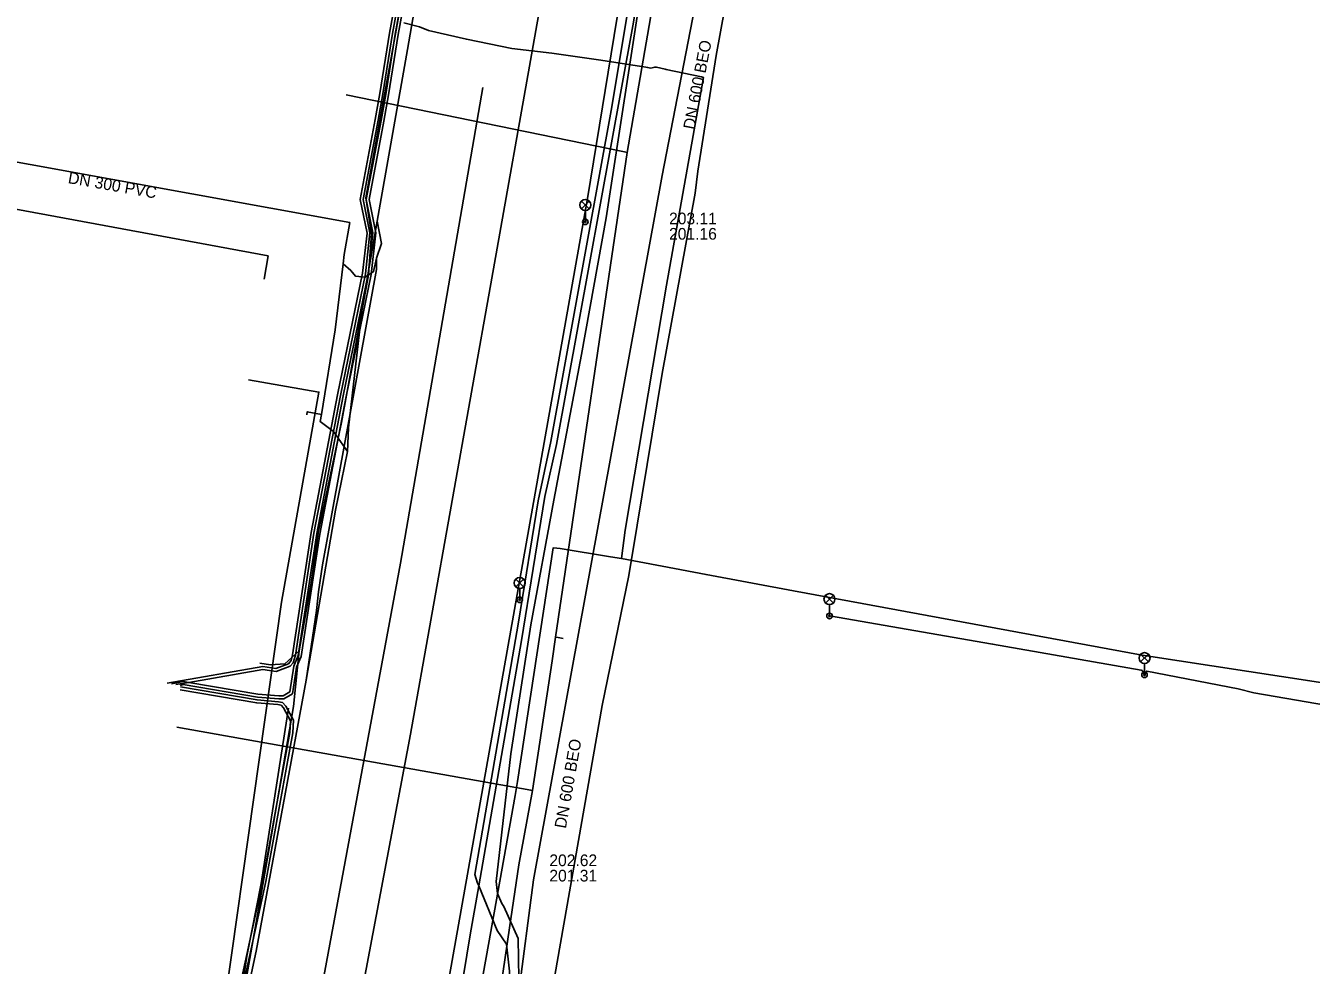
# Model space of a CAD drawing. Extents: x -596228 to -595156, y -1161235 to -1159373.
# Drawn here: x -595929.1 to -595841.1, y -1160278.8 to -1160214.5 of the extents above; entities that cross this region are included whole.
import ezdxf

# ---------------------------------------------------------------- set-up
doc = ezdxf.new("R2010")
doc.units = 0
for name, color, linetype in [('Vrstva 1', 7, 'Continuous'), ('Vrstva 12', 7, 'Continuous'), ('Vrstva 14', 7, 'Continuous'), ('Vrstva 19', 7, 'Continuous'), ('Vrstva 33', 7, 'Continuous'), ('Vrstva 4', 7, 'Continuous'), ('Vrstva 42', 7, 'Continuous'), ('Vrstva 44', 7, 'Continuous'), ('Vrstva 5', 7, 'Continuous'), ('Vrstva 53', 7, 'Continuous'), ('Vrstva 55', 7, 'Continuous'), ('Vrstva 58', 7, 'Continuous'), ('Vrstva 9', 7, 'Continuous')]:
    doc.layers.add(name, color=color, linetype=linetype)

msp = doc.modelspace()

# ---------------------------------------------------------------- linework, layer by layer
at = {"layer": 'Vrstva 1'}
for p, q in [((-595876.82, -1160179.87), (-595885.54, -1160224.74)), ((-595897.82, -1160218.72), (-595903.46, -1160251.27)), ((-595885.54, -1160224.74), (-595894.35, -1160272.94)), ((-595912.774, -1160231.832), (-595912.502, -1160230.231)), ((-595903.46, -1160251.27), (-595910.91, -1160291.43)), ((-595894.35, -1160272.94), (-595897.18, -1160294.69))]:
    msp.add_line(p, q, dxfattribs=at)
msp.add_lwpolyline([(-595912.502, -1160230.231), (-595937.093, -1160225.712), (-595938.437, -1160225.792)], dxfattribs=at)
at = {"layer": 'Vrstva 12'}
for p, q in [((-595905.09, -1160230.41), (-595904.75, -1160229.39)), ((-595907.09, -1160243.62), (-595908.03, -1160242.26)), ((-595909.07, -1160253.23), (-595909.2, -1160254.51)), ((-595909.2, -1160254.51), (-595909.92, -1160259.27)), ((-595909.92, -1160259.27), (-595913.327, -1160277.82)), ((-595913.327, -1160277.82), (-595916.466, -1160292.479))]:
    msp.add_line(p, q, dxfattribs=at)
for points in [[(-595897.36, -1160184.72), (-595897.52, -1160185.49), (-595898.28, -1160189.11), (-595902.98, -1160216.12), (-595905.04, -1160227.87), (-595904.75, -1160229.39)], [(-595906.85, -1160231.25), (-595907.387, -1160230.78), (-595907.31, -1160230.14), (-595906.92, -1160227.97), (-595939.63, -1160222.04), (-595961.4, -1160213.41), (-595962.62, -1160212.93), (-595961.32, -1160205.66)], [(-595905.04, -1160227.87), (-595906.05, -1160233.63), (-595906.1, -1160234.06), (-595907.02, -1160242.01), (-595907.09, -1160243.62)], [(-595909.07, -1160253.23), (-595908.79, -1160251.39), (-595905.09, -1160231.17), (-595905.09, -1160230.41)], [(-595908.86, -1160241.09), (-595907.93, -1160235.31), (-595907.387, -1160230.78)], [(-595905.86, -1160231.69), (-595906.54, -1160231.63), (-595906.85, -1160231.25)], [(-595905.09, -1160230.41), (-595905.3, -1160231.32), (-595905.86, -1160231.69)], [(-595908.86, -1160241.09), (-595909.84, -1160240.91), (-595909.87, -1160241.11)], [(-595908.03, -1160242.26), (-595908.94, -1160241.58), (-595908.86, -1160241.09)], [(-595907.09, -1160243.62), (-595907.89, -1160247.65), (-595909.92, -1160259.27)]]:
    msp.add_lwpolyline(points, dxfattribs=at)
at = {"layer": 'Vrstva 14'}
for p, q in [((-595892.847, -1160256.335), (-595892.657, -1160256.359)), ((-595892.657, -1160256.359), (-595892.328, -1160256.414))]:
    msp.add_line(p, q, dxfattribs=at)
for points in [[(-595903.525, -1160327.591), (-595903.438, -1160327.11), (-595895.992, -1160276.218), (-595895.362, -1160271.913), (-595894.416, -1160266.829), (-595893.077, -1160257.958), (-595892.847, -1160256.335), (-595887.94, -1160223.167), (-595881.65, -1160186.81), (-595876.814, -1160159.541), (-595869.649, -1160117.522), (-595863.209, -1160078.856), (-595858.091, -1160048.124), (-595857.576, -1160045.207), (-595855.994, -1160045.422), (-595855.543, -1160042.523), (-595857.05, -1160042.292), (-595850.5, -1160006.311), (-595840.026, -1160007.969)], [(-595887.94, -1160223.167), (-595888.124, -1160223.122), (-595907.174, -1160219.223)], [(-595894.416, -1160266.829), (-595894.54, -1160266.81), (-595918.761, -1160262.489)]]:
    msp.add_lwpolyline(points, dxfattribs=at)
at = {"layer": 'Vrstva 19'}
for points in [[(-595903.221, -1160214.288), (-595902.141, -1160214.568), (-595901.538, -1160214.811), (-595898.944, -1160215.422), (-595895.836, -1160216.053), (-595893.093, -1160216.381), (-595889.745, -1160216.854), (-595886.651, -1160217.335), (-595886.538, -1160217.348), (-595886.31, -1160217.396), (-595886.044, -1160217.328), (-595885.94, -1160217.34), (-595885.329, -1160217.474), (-595885.273, -1160217.492), (-595882.844, -1160217.996), (-595882.722, -1160218.029), (-595885.239, -1160232.238), (-595888.066, -1160249.019), (-595888.326, -1160250.942)], [(-595885.548, -1160251.465), (-595888.326, -1160250.942), (-595889.076, -1160250.833), (-595892.522, -1160250.265), (-595892.744, -1160250.249), (-595892.999, -1160250.212), (-595895.437, -1160266.212), (-595895.603, -1160267.172), (-595897.424, -1160277.35), (-595899.243, -1160287.517)], [(-595807.996, -1160263.637), (-595810.557, -1160263.662), (-595816.559, -1160263.81), (-595837.554, -1160259.982), (-595840.612, -1160259.413), (-595852.684, -1160257.565), (-595876.553, -1160253.153), (-595882.538, -1160252.052), (-595885.548, -1160251.465)]]:
    msp.add_lwpolyline(points, dxfattribs=at)
at = {"layer": 'Vrstva 33'}
for p, q in [((-595891.065, -1160226.495), (-595890.535, -1160227.025)), ((-595891.065, -1160227.025), (-595890.535, -1160226.495)), ((-595890.8, -1160227.91), (-595890.8, -1160227.135)), ((-595895.559, -1160252.36), (-595895.029, -1160252.89)), ((-595895.559, -1160252.89), (-595895.029, -1160252.36)), ((-595895.294, -1160253.775), (-595895.294, -1160253)), ((-595874.355, -1160253.465), (-595873.825, -1160253.995)), ((-595874.355, -1160253.995), (-595873.825, -1160253.465)), ((-595874.09, -1160254.88), (-595874.09, -1160254.105)), ((-595852.791, -1160257.498), (-595852.261, -1160258.028)), ((-595852.791, -1160258.028), (-595852.261, -1160257.498)), ((-595852.526, -1160258.913), (-595852.526, -1160258.138))]:
    msp.add_line(p, q, dxfattribs=at)
for centre, radius in [((-595890.8, -1160226.76), 0.375), ((-595890.8, -1160227.91), 0.19), ((-595890.8, -1160227.91), 0.05), ((-595895.294, -1160252.625), 0.375), ((-595895.294, -1160253.775), 0.19), ((-595895.294, -1160253.775), 0.05), ((-595874.09, -1160253.73), 0.375), ((-595874.09, -1160254.88), 0.19), ((-595874.09, -1160254.88), 0.05), ((-595852.526, -1160257.763), 0.375), ((-595852.526, -1160258.913), 0.19), ((-595852.526, -1160258.913), 0.05)]:
    msp.add_circle(centre, radius, dxfattribs=at)
at = {"layer": 'Vrstva 42'}
for points in [[(-595899.339, -1160297.503), (-595902.099, -1160297.56), (-595902.383, -1160297.165), (-595902.586, -1160296.883), (-595902.568, -1160296.769), (-595901.316, -1160288.727), (-595900.471, -1160287.553), (-595898.687, -1160276.707), (-595898.101, -1160273.351), (-595895.17, -1160256.55), (-595893.577, -1160246.717), (-595892.781, -1160243.14), (-595887.556, -1160214.494), (-595883.249, -1160189.231), (-595883.208, -1160189), (-595882.655, -1160185.86), (-595879.849, -1160169.95), (-595878.786, -1160163.811), (-595878.313, -1160161.147), (-595878.278, -1160160.95), (-595875.884, -1160147.461), (-595871.512, -1160122.724)], [(-595899.318, -1160297.883), (-595899.891, -1160298.432), (-595899.423, -1160299.009), (-595897.224, -1160298.688), (-595896.375, -1160297.645), (-595896.521, -1160294.611), (-595896.622, -1160292.035), (-595896.678, -1160291.316), (-595895.995, -1160279.177), (-595896.207, -1160277.347), (-595896.845, -1160276.413), (-595898.101, -1160273.351), (-595898.174, -1160273.174), (-595898.37, -1160272.566), (-595895.372, -1160255.298), (-595894.03, -1160247.01), (-595893.153, -1160242.953), (-595888.976, -1160220.051), (-595884.001, -1160189.966)], [(-595902.605, -1160206.328), (-595904.206, -1160214.999), (-595904.856, -1160219.13), (-595905.175, -1160220.916), (-595906.206, -1160226.392), (-595905.743, -1160228.683), (-595906.057, -1160231.433), (-595907.764, -1160239.752), (-595909.576, -1160249.179), (-595910.847, -1160257.535), (-595910.946, -1160257.929), (-595911.122, -1160258.156), (-595911.981, -1160258.477), (-595912.871, -1160258.349), (-595919.421, -1160259.479)], [(-595902.212, -1160206.397), (-595903.811, -1160215.067), (-595904.461, -1160219.197), (-595904.782, -1160220.988), (-595905.798, -1160226.389), (-595905.339, -1160228.666), (-595905.661, -1160231.496), (-595907.372, -1160239.83), (-595909.181, -1160249.247), (-595910.451, -1160257.595), (-595910.764, -1160258.321), (-595911.032, -1160260.078), (-595911.483, -1160260.346), (-595911.775, -1160260.351), (-595913.212, -1160260.232), (-595917.946, -1160259.427), (-595918.337, -1160259.361), (-595919.13, -1160259.53)], [(-595902.409, -1160206.363), (-595904.009, -1160215.033), (-595904.659, -1160219.163), (-595904.978, -1160220.952), (-595906.002, -1160226.391), (-595905.541, -1160228.674), (-595905.859, -1160231.464), (-595907.568, -1160239.791), (-595909.379, -1160249.213), (-595910.649, -1160257.565), (-595910.809, -1160258.078), (-595910.998, -1160258.324), (-595911.959, -1160258.683), (-595912.869, -1160258.551), (-595917.946, -1160259.427), (-595918.839, -1160259.581)], [(-595902.015, -1160206.432), (-595903.614, -1160215.101), (-595904.264, -1160219.23), (-595904.585, -1160221.024), (-595905.594, -1160226.388), (-595905.137, -1160228.657), (-595905.463, -1160231.527), (-595907.176, -1160239.869), (-595908.984, -1160249.281), (-595910.257, -1160257.651), (-595910.57, -1160258.376), (-595910.848, -1160260.202), (-595911.427, -1160260.545), (-595911.782, -1160260.551), (-595913.237, -1160260.431), (-595918.333, -1160259.564), (-595918.543, -1160259.635)], [(-595918.537, -1160259.935), (-595913.288, -1160260.828), (-595911.837, -1160260.948), (-595911.623, -1160260.992), (-595911.462, -1160261.169), (-595910.972, -1160262.063), (-595911.019, -1160262.848), (-595911.438, -1160265.082), (-595912.868, -1160273.011), (-595914.988, -1160282.762), (-595915.239, -1160284.476), (-595915.239, -1160284.478), (-595915.289, -1160284.826)], [(-595918.504, -1160259.738), (-595913.263, -1160260.629), (-595911.808, -1160260.75), (-595911.519, -1160260.809), (-595911.298, -1160261.051), (-595910.768, -1160262.017), (-595910.821, -1160262.872), (-595911.242, -1160265.118), (-595912.672, -1160273.05), (-595914.792, -1160282.798), (-595915.041, -1160284.502), (-595915.041, -1160284.504), (-595915.091, -1160284.854)]]:
    msp.add_lwpolyline(points, dxfattribs=at)
at = {"layer": 'Vrstva 44'}
for points in [[(-595896.897, -1160273.045), (-595895.909, -1160264.308), (-595894.529, -1160255.491), (-595892.955, -1160246.953), (-595891.073, -1160236.98), (-595889.376, -1160227.647), (-595886.84, -1160211.177), (-595885.783, -1160204.31), (-595884.451, -1160196.692), (-595882.21, -1160184.038), (-595880.223, -1160171.529), (-595878.837, -1160163.768), (-595878.228, -1160160.447), (-595878.1, -1160159.1), (-595877.88, -1160157.51)], [(-595896.897, -1160273.045), (-595896.806, -1160273.86), (-595896.521, -1160274.563), (-595896.383, -1160274.768), (-595895.399, -1160276.958), (-595895.348, -1160279.684)]]:
    msp.add_lwpolyline(points, dxfattribs=at)
at = {"layer": 'Vrstva 5'}
msp.add_line((-595911.59, -1160253.94), (-595915.382, -1160280.667), dxfattribs=at)
msp.add_lwpolyline([(-595913.851, -1160238.732), (-595909.039, -1160239.565), (-595911.59, -1160253.94)], dxfattribs=at)
at = {"layer": 'Vrstva 53'}
for points in [[(-595878.72, -1160160.38), (-595878.9, -1160160.76), (-595879.19, -1160160.96), (-595882.85, -1160160.12), (-595885.65, -1160159.55), (-595888.42, -1160159.22), (-595893.19, -1160158.25), (-595893.53, -1160158.31), (-595893.95, -1160158.7), (-595894.87, -1160163.74), (-595896.89, -1160175), (-595897.42, -1160178.86), (-595898.79, -1160185.95), (-595898.99, -1160187.07), (-595901.26, -1160200.17), (-595903.5, -1160213.4), (-595905.82, -1160226.28), (-595905.44, -1160228.74)], [(-595905.44, -1160228.74), (-595905.65, -1160231.54), (-595907.5, -1160241.64), (-595909.07, -1160249.09), (-595909.56, -1160252.61), (-595910.39, -1160257.27)], [(-595910.39, -1160257.27), (-595910.65, -1160259.73), (-595910.78, -1160261.08), (-595912.45, -1160270.8), (-595914.12, -1160280.39), (-595914.76, -1160285.45)], [(-595910.39, -1160257.27), (-595911.37, -1160258.16), (-595912.361, -1160258.234), (-595913.09, -1160258.12)]]:
    msp.add_lwpolyline(points, dxfattribs=at)
at = {"layer": 'Vrstva 55'}
for points in [[(-595901.722, -1160303.649), (-595901.92, -1160299.12), (-595902.19, -1160291.297), (-595890.66, -1160226.32), (-595886.19, -1160198.97), (-595881.04, -1160171.41), (-595876.29, -1160143.99), (-595871.58, -1160116.92), (-595868.39, -1160099.39), (-595861.162, -1160062.826), (-595862.06, -1160062.41)], [(-595802.755, -1160261.425), (-595802.697, -1160261.658), (-595802.967, -1160261.847), (-595803.854, -1160262.507), (-595804.43, -1160265.917), (-595804.798, -1160266.069), (-595809.389, -1160265.892), (-595809.742, -1160265.803), (-595809.98, -1160266.16), (-595810.11, -1160265.71), (-595811.32, -1160265.47), (-595816.12, -1160265.15), (-595830.541, -1160262.523), (-595830.72, -1160262.96), (-595830.85, -1160262.49), (-595838.54, -1160261.25), (-595845.04, -1160260.15), (-595846.12, -1160259.87), (-595852.379, -1160258.654), (-595852.526, -1160258.913), (-595852.693, -1160258.612), (-595852.76, -1160258.58), (-595862.93, -1160256.8), (-595874.09, -1160254.88)]]:
    msp.add_lwpolyline(points, dxfattribs=at)
at = {"layer": 'Vrstva 58'}
for points in [[(-595892.89, -1160279.48), (-595889.65, -1160261.01), (-595887.82, -1160252.11), (-595887.26, -1160248.67), (-595885.55, -1160238.3), (-595883.29, -1160225.96), (-595883.1, -1160224.44), (-595881.84, -1160216.53), (-595879.51, -1160203.81)], [(-595892.89, -1160279.48), (-595889.65, -1160261.01), (-595887.82, -1160252.11), (-595887.26, -1160248.67), (-595885.55, -1160238.3), (-595883.29, -1160225.96), (-595883.1, -1160224.44), (-595881.84, -1160216.53), (-595879.51, -1160203.81)], [(-595919.8, -1160298.61), (-595917.65, -1160298.61), (-595917.47, -1160298.35), (-595915.38, -1160291.05), (-595914.51, -1160286.13), (-595914.88, -1160284.32), (-595913.96, -1160278.16), (-595912.99, -1160273.19), (-595911.12, -1160261.2)]]:
    msp.add_lwpolyline(points, dxfattribs=at)
at = {"layer": 'Vrstva 9'}
for p, q in [((-595895.414, -1160221.746), (-595896.03, -1160225.22)), ((-595896.03, -1160225.22), (-595897.199, -1160231.766)), ((-595897.199, -1160231.766), (-595902.77, -1160262.96))]:
    msp.add_line(p, q, dxfattribs=at)
for points in [[(-595889.06, -1160185.9), (-595890.86, -1160196.053), (-595895.414, -1160221.746)], [(-595902.77, -1160262.96), (-595907.181, -1160286.303), (-595907.98, -1160290.528)]]:
    msp.add_lwpolyline(points, dxfattribs=at)

# ---------------------------------------------------------------- texts
at = {"layer": 'Vrstva 4'}
for s, rotation, p in [('DN 600 BEO', 79, (-595883.328, -1160221.641)), ('DN 300 PVC', 350, (-595926.252, -1160225.259)), ('DN 600 BEO', 80, (-595892.133, -1160269.462))]:
    msp.add_text(s, height=0.8, rotation=rotation, dxfattribs=at).set_placement(p)
for s, p in [('203.11', (-595885.07, -1160228.084)), ('201.16', (-595885.07, -1160229.134)), ('202.62', (-595893.263, -1160272)), ('201.31', (-595893.263, -1160273.05))]:
    msp.add_text(s, height=0.8, dxfattribs=at).set_placement(p)

doc.saveas('drawing.dxf')
